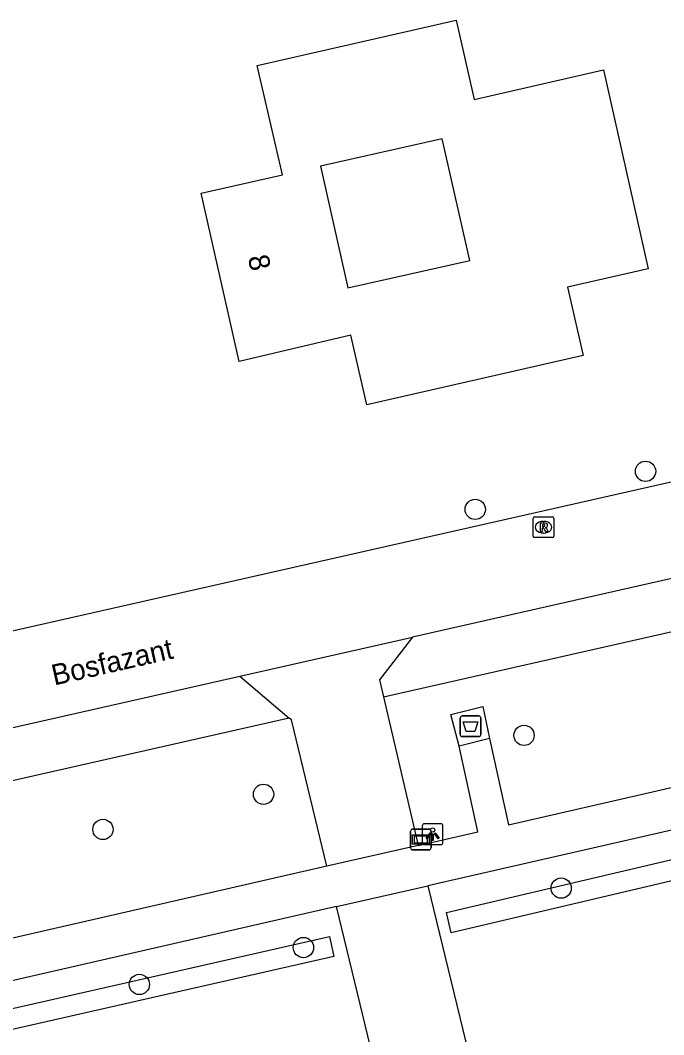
# Model space of a CAD drawing. Extents: x 156664 to 157568, y 383571 to 384421.
# Drawn here: x 156873.66 to 156904.67, y 384078.47 to 384127.38 of the extents above; entities that cross this region are included whole.
import ezdxf

# ---------------------------------------------------------------- set-up
doc = ezdxf.new("R2010")
doc.units = 0
for name, color, linetype in [('IMGEO_Afval_apart_plaats', 7, 'Continuous'), ('IMGEO_Boom', 7, 'Continuous'), ('IMGEO_Haag', 7, 'Continuous'), ('IMGEO_Lichtpunt', 7, 'Continuous'), ('IMGEO_Openbare_ruimte_label', 7, 'Continuous'), ('IMGEO_Pand', 7, 'Continuous'), ('IMGEO_Pand_nummerreeks', 7, 'Continuous'), ('IMGEO_Parkeervlak_open', 7, 'Continuous'), ('IMGEO_Rijbaan_lokaal_open', 7, 'Continuous'), ('IMGEO_Rioolput', 7, 'Continuous'), ('IMGEO_Verklikker', 7, 'Continuous'), ('IMGEO_Voetpad_gesloten', 7, 'Continuous'), ('IMGEO_Voetpad_open', 7, 'Continuous')]:
    doc.layers.add(name, color=color, linetype=linetype)

msp = doc.modelspace()

# ---------------------------------------------------------------- linework, layer by layer
at = {"layer": 'IMGEO_Afval_apart_plaats'}
for p, q in [((156894.865, 384092.938), (156894.865, 384093.738)), ((156894.865, 384093.738), (156894.865, 384092.938)), ((156894.965, 384093.838), (156895.755, 384093.838)), ((156895.755, 384093.838), (156894.965, 384093.838)), ((156895.855, 384093.738), (156895.855, 384092.938)), ((156895.855, 384092.938), (156895.855, 384093.738)), ((156895.755, 384092.838), (156894.965, 384092.838)), ((156894.965, 384092.838), (156895.755, 384092.838))]:
    msp.add_line(p, q, dxfattribs=at)
msp.add_lwpolyline([(156895.008, 384093.552), (156895.712, 384093.552), (156895.563, 384093.082), (156895.157, 384093.082), (156895.008, 384093.552)], dxfattribs=at)
for centre, start, end in [((156894.965, 384093.738), 90, 180), ((156894.965, 384093.738), 90, 180), ((156895.755, 384093.738), 0, 90), ((156895.755, 384093.738), 360, 90), ((156894.965, 384092.938), 180, 270), ((156894.965, 384092.938), 180, 270), ((156895.755, 384092.938), 270, 0), ((156895.755, 384092.938), 270, 0)]:
    msp.add_arc(centre, 0.1, start, end, dxfattribs=at)
at = {"layer": 'IMGEO_Boom'}
for centre in [(156903.799, 384105.629), (156895.589, 384103.795), (156897.94, 384092.899), (156885.385, 384090.056), (156877.644, 384088.362), (156899.731, 384085.535), (156887.305, 384082.666), (156879.398, 384080.89)]:
    msp.add_circle(centre, 0.489, dxfattribs=at)
at = {"layer": 'IMGEO_Haag'}
for points in [[(156911.133, 384087.316), (156894.424, 384083.379), (156894.195, 384084.352), (156910.882, 384088.284), (156914.157, 384089.056), (156914.386, 384088.082), (156911.133, 384087.316)], [(156842.768, 384071.784), (156842.547, 384072.759), (156888.556, 384083.206), (156888.777, 384082.231), (156842.768, 384071.784)]]:
    msp.add_lwpolyline(points, dxfattribs=at)
at = {"layer": 'IMGEO_Lichtpunt'}
for p, q in [((156893.037, 384088.538), (156893.037, 384087.731)), ((156893.037, 384088.538), (156893.037, 384087.731)), ((156893.939, 384088.633), (156893.131, 384088.633)), ((156893.939, 384088.633), (156893.131, 384088.633)), ((156894.033, 384087.731), (156894.033, 384088.538)), ((156894.033, 384087.731), (156894.033, 384088.538)), ((156893.131, 384087.637), (156893.939, 384087.637)), ((156893.131, 384087.637), (156893.939, 384087.637))]:
    msp.add_line(p, q, dxfattribs=at)
for points in [[(156893.411, 384088.202), (156893.45, 384088.174), (156893.262, 384087.912), (156893.224, 384087.939), (156893.411, 384088.202)], [(156893.513, 384088.154), (156893.56, 384088.154), (156893.56, 384087.832), (156893.513, 384087.832), (156893.513, 384088.154)], [(156893.623, 384088.174), (156893.661, 384088.201), (156893.848, 384087.939), (156893.809, 384087.911), (156893.623, 384088.174)]]:
    msp.add_lwpolyline(points, dxfattribs=at)
msp.add_circle((156893.536, 384088.336), 0.0994, dxfattribs=at)
for centre, start, end in [((156893.131, 384088.538), 90, 180), ((156893.131, 384088.538), 90, 180), ((156893.939, 384088.538), 0, 90), ((156893.939, 384088.538), 0, 90), ((156893.131, 384087.731), 180, 270), ((156893.131, 384087.731), 180, 270), ((156893.939, 384087.731), 270, 0), ((156893.939, 384087.731), 270, 360)]:
    msp.add_arc(centre, 0.0946, start, end, dxfattribs=at)
at = {"layer": 'IMGEO_Pand'}
for points in [[(156901.773, 384124.986), (156903.928, 384115.39), (156900.03, 384114.513), (156900.787, 384111.213), (156890.356, 384108.831), (156889.588, 384112.196), (156884.217, 384110.925), (156882.383, 384119.039), (156886.299, 384119.925), (156885.078, 384125.203), (156894.667, 384127.376), (156895.531, 384123.562), (156901.773, 384124.986)], [(156888.123, 384120.338), (156889.45, 384114.472), (156895.321, 384115.8), (156893.994, 384121.666), (156888.123, 384120.338)]]:
    msp.add_lwpolyline(points, dxfattribs=at)
at = {"layer": 'IMGEO_Parkeervlak_open'}
for points in [[(156891.161, 384094.76), (156941.38, 384106.125)], [(156886.622, 384093.732), (156825.408, 384079.879), (156824.856, 384082.318)]]:
    msp.add_lwpolyline(points, dxfattribs=at)
at = {"layer": 'IMGEO_Rijbaan_lokaal_open'}
for points in [[(156942.411, 384108.921), (156892.56, 384097.639)], [(156914.342, 384107.209), (156854.008, 384093.566)], [(156884.236, 384095.756), (156892.56, 384097.639)], [(156892.56, 384097.639), (156890.971, 384095.573), (156891.161, 384094.76)], [(156824.856, 384082.318), (156884.236, 384095.756)], [(156884.236, 384095.756), (156886.622, 384093.732)], [(156891.161, 384094.76), (156892.833, 384087.596)], [(156888.427, 384086.586), (156886.731, 384093.64), (156886.622, 384093.732)], [(156892.833, 384087.596), (156888.427, 384086.586)], [(156888.906, 384084.645), (156893.311, 384085.637)], [(156893.311, 384085.637), (156895.679, 384075.854), (156897.002, 384076.155), (156897.057, 384075.914)], [(156889.977, 384074.171), (156889.94, 384074.329), (156891.301, 384074.755), (156888.906, 384084.645)]]:
    msp.add_lwpolyline(points, dxfattribs=at)
at = {"layer": 'IMGEO_Rioolput'}
for p, q in [((156898.452, 384103.435), (156899.304, 384103.435)), ((156898.377, 384102.509), (156898.377, 384103.361)), ((156898.865, 384103.215), (156898.89, 384103.215)), ((156899.378, 384103.361), (156899.378, 384102.509)), ((156899.304, 384102.435), (156898.452, 384102.435)), ((156898.888, 384102.655), (156898.863, 384102.655))]:
    msp.add_line(p, q, dxfattribs=at)
for points in [[(156898.452, 384103.435), (156899.304, 384103.435)], [(156898.377, 384102.509), (156898.377, 384103.361)], [(156898.966, 384103.133), (156898.714, 384103.135), (156898.714, 384102.735)], [(156898.714, 384102.735), (156898.838, 384102.735), (156898.838, 384102.897), (156898.849, 384102.897)], [(156898.892, 384103.054), (156898.838, 384103.054), (156898.838, 384102.973)], [(156898.838, 384102.973), (156898.89, 384102.973)], [(156899.378, 384103.361), (156899.378, 384102.509)], [(156899.304, 384102.435), (156898.452, 384102.435)], [(156898.896, 384102.868), (156898.967, 384102.735), (156899.107, 384102.735), (156899.042, 384102.861)]]:
    msp.add_lwpolyline(points, dxfattribs=at)
for centre, radius, start, end in [((156898.454, 384103.359), 0.0765, 91.552, 178.448), ((156898.454, 384103.359), 0.0765, 91.552, 178.448), ((156899.302, 384103.359), 0.0765, 1.552, 88.448), ((156899.302, 384103.359), 0.0765, 1.552, 88.448), ((156898.848, 384102.844), 0.0533, 26.0293, 88.6989), ((156898.874, 384103.162), 0.19, 274.7715, 282.9687), ((156898.898, 384102.958), 0.0964, 77.0061, 93.1865), ((156898.912, 384103.015), 0.0378, 276.6634, 79.6772), ((156898.965, 384103.023), 0.109, 350.3612, 89.416), ((156898.963, 384103.023), 0.112, 277.5842, 350.9817), ((156898.947, 384102.808), 0.108, 29.5134, 73.7905), ((156898.454, 384102.511), 0.0765, 181.552, 268.448), ((156898.454, 384102.511), 0.0765, 181.552, 268.448), ((156899.302, 384102.511), 0.0765, 271.552, 358.448), ((156899.302, 384102.511), 0.0765, 271.552, 358.448)]:
    msp.add_arc(centre, radius, start, end, dxfattribs=at)
for centre, major_axis, ratio, start_param, end_param in [((156898.864, 384102.935), (-0.387, 0.002), 0.722429, 4.712389, 7.853982), ((156898.889, 384102.935), (-0.39, 0.002), 0.717154, 1.570796, 4.712389)]:
    msp.add_ellipse(centre, major_axis=major_axis, ratio=ratio, start_param=start_param, end_param=end_param, dxfattribs=at)
at = {"layer": 'IMGEO_Verklikker'}
for p, q in [((156892.471, 384087.478), (156892.471, 384088.278)), ((156892.471, 384088.278), (156892.471, 384087.478)), ((156892.571, 384088.378), (156893.361, 384088.378)), ((156893.361, 384088.378), (156892.571, 384088.378)), ((156893.461, 384088.278), (156893.461, 384087.478)), ((156893.461, 384087.478), (156893.461, 384088.278)), ((156893.361, 384087.378), (156892.571, 384087.378)), ((156892.571, 384087.378), (156893.361, 384087.378))]:
    msp.add_line(p, q, dxfattribs=at)
for points in [[(156892.572, 384088.11), (156893.36, 384088.11), (156893.36, 384087.646), (156892.572, 384087.646), (156892.572, 384088.11)], [(156892.637, 384088.045), (156892.637, 384087.711), (156893.295, 384087.711), (156893.295, 384088.045), (156892.637, 384088.045)]]:
    msp.add_lwpolyline(points, dxfattribs=at)
for centre, start, end in [((156892.571, 384088.278), 90, 180), ((156892.571, 384088.278), 90, 180), ((156893.361, 384088.278), 0, 90), ((156893.361, 384088.278), 360, 90), ((156892.571, 384087.478), 180, 270), ((156892.571, 384087.478), 180, 270), ((156893.361, 384087.478), 270, 0), ((156893.361, 384087.478), 270, 0)]:
    msp.add_arc(centre, 0.1, start, end, dxfattribs=at)
at = {"layer": 'IMGEO_Voetpad_gesloten'}
for points in [[(156894.812, 384092.384), (156894.413, 384093.909), (156895.952, 384094.287), (156896.269, 384092.742)], [(156896.269, 384092.742), (156894.812, 384092.384)]]:
    msp.add_lwpolyline(points, dxfattribs=at)
at = {"layer": 'IMGEO_Voetpad_open'}
for points in [[(156896.269, 384092.742), (156897.184, 384088.584), (156917.305, 384093.191), (156943.045, 384099.085)], [(156943.484, 384097.16), (156932.125, 384094.547), (156929.047, 384093.838), (156918.727, 384091.464), (156910.543, 384089.588), (156893.311, 384085.637)], [(156892.833, 384087.596), (156895.715, 384088.254), (156894.812, 384092.384)], [(156888.427, 384086.586), (156811.028, 384068.852)], [(156888.906, 384084.645), (156834.367, 384072.163)]]:
    msp.add_lwpolyline(points, dxfattribs=at)

# ---------------------------------------------------------------- texts
at = {"layer": 'IMGEO_Openbare_ruimte_label'}
msp.add_text('Bosfazant', height=1, rotation=12.7712, dxfattribs=at).set_placement((156875.294, 384095.3))
at = {"layer": 'IMGEO_Pand_nummerreeks'}
msp.add_text('8', height=1, rotation=282.5361, dxfattribs=at).set_placement((156884.62, 384115.952))

doc.saveas('drawing.dxf')
